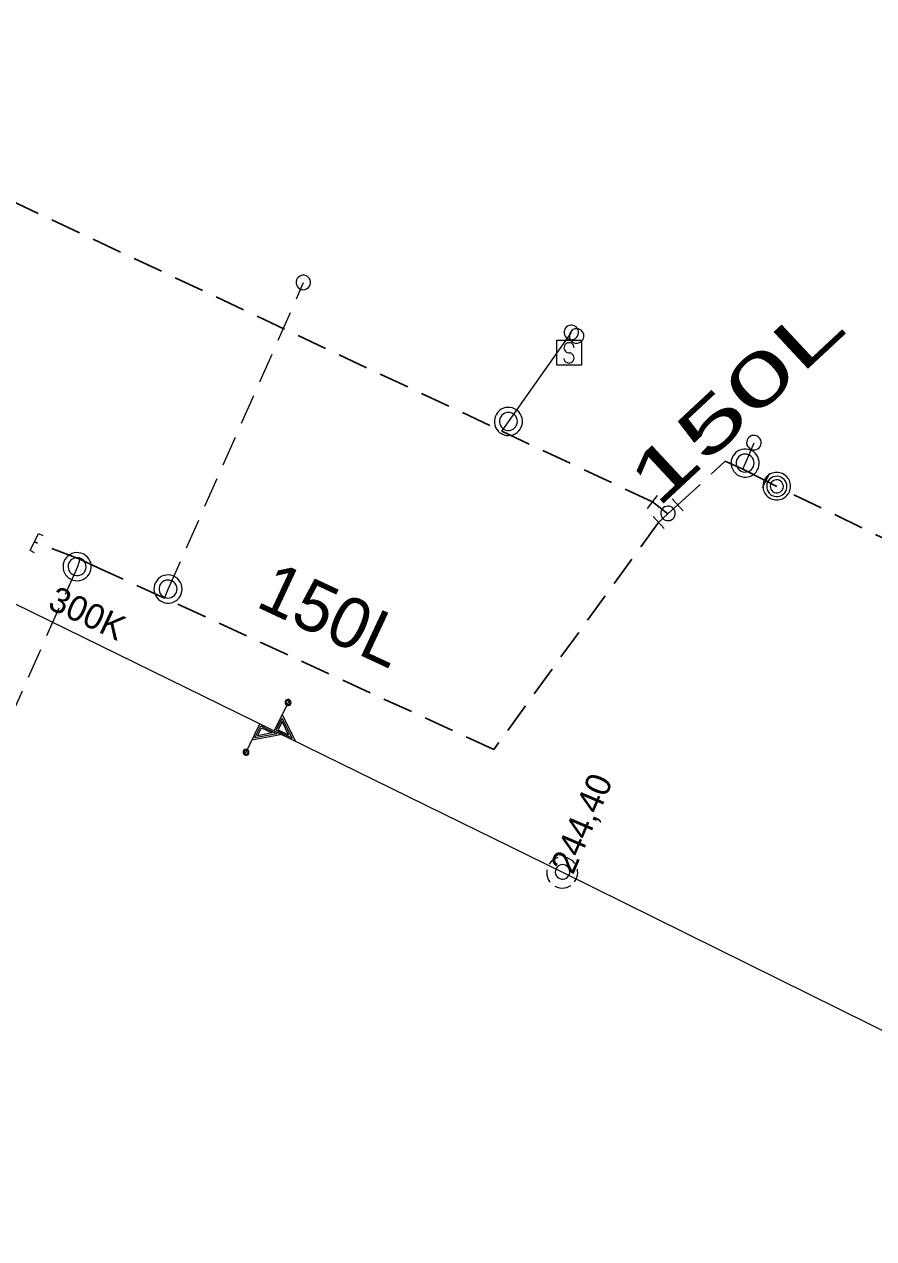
# Model space of a CAD drawing. Extents: x -735085 to -733500, y -1044153 to -1043402.
# Drawn here: x -734784.97 to -734758, y -1043597.02 to -1043558.45 of the extents above; entities that cross this region are included whole.
import ezdxf

# ---------------------------------------------------------------- set-up
doc = ezdxf.new("R2010")
doc.units = 0
doc.header["$LTSCALE"] = 0.32
doc.linetypes.add('MEDIUM_DASHED', pattern=[4.5, 3, -1.5])
doc.layers.add('15', color=7, linetype='Continuous')
doc.layers.add('16', color=7, linetype='Continuous')
for name, color, linetype, lineweight in [('18', 7, 'Continuous', 13), ('20', 7, 'Continuous', 13), ('8', 7, 'Continuous', 13)]:
    doc.layers.add(name, color=color, linetype=linetype, lineweight=lineweight)

msp = doc.modelspace()

# ---------------------------------------------------------------- linework, layer by layer
at = {"layer": '18'}
for points in [[(-734776.554, -1043579.904), (-734777.036, -1043580.888), (-734776.344, -1043581.227), (-734776.781, -1043580.369)], [(-734776.788, -1043580.498), (-734776.971, -1043580.871), (-734776.463, -1043581.121), (-734776.787, -1043580.496)], [(-734777.97, -1043581.655), (-734777.488, -1043580.672), (-734776.797, -1043581.011), (-734777.743, -1043581.191)], [(-734777.646, -1043581.107), (-734777.463, -1043580.734), (-734776.955, -1043580.983), (-734777.646, -1043581.108)], [(-734777.567, -1043581.052), (-734777.438, -1043580.79), (-734777.104, -1043580.954), (-734777.568, -1043581.052)], [(-734776.782, -1043580.593), (-734776.911, -1043580.855), (-734776.578, -1043581.019), (-734776.783, -1043580.593)], [(-734768.032, -1043584.917), (-734768.103, -1043584.945), (-734768.169, -1043584.984), (-734768.23, -1043585.032), (-734768.281, -1043585.089), (-734768.304, -1043585.123)], [(-734767.49, -1043585.1), (-734767.541, -1043585.042), (-734767.598, -1043584.992), (-734767.664, -1043584.951), (-734767.735, -1043584.922), (-734767.784, -1043584.908)], [(-734768.377, -1043585.309), (-734768.382, -1043585.386), (-734768.377, -1043585.463), (-734768.36, -1043585.538), (-734768.331, -1043585.609), (-734768.291, -1043585.675), (-734768.276, -1043585.697)], [(-734767.495, -1043585.686), (-734767.455, -1043585.621), (-734767.424, -1043585.551), (-734767.404, -1043585.476), (-734767.397, -1043585.4), (-734767.402, -1043585.323), (-734767.407, -1043585.288)], [(-734768.119, -1043585.826), (-734768.049, -1043585.857), (-734767.973, -1043585.876), (-734767.897, -1043585.883), (-734767.821, -1043585.878), (-734767.745, -1043585.861), (-734767.674, -1043585.833), (-734767.614, -1043585.798)]]:
    msp.add_lwpolyline(points, dxfattribs=at)
for points in [[(-734776.51, -1043580.031), (-734776.501, -1043579.998), (-734776.503, -1043579.965), (-734776.517, -1043579.935), (-734776.542, -1043579.911), (-734776.572, -1043579.898), (-734776.605, -1043579.896), (-734776.638, -1043579.906), (-734776.665, -1043579.926), (-734776.683, -1043579.954), (-734776.689, -1043579.987), (-734776.684, -1043580.02), (-734776.668, -1043580.049), (-734776.642, -1043580.071), (-734776.611, -1043580.082), (-734776.578, -1043580.082), (-734776.546, -1043580.07), (-734776.521, -1043580.048)], [(-734776.535, -1043580.021), (-734776.528, -1043579.993), (-734776.533, -1043579.965), (-734776.549, -1043579.942), (-734776.574, -1043579.927), (-734776.601, -1043579.924), (-734776.628, -1043579.931), (-734776.65, -1043579.95), (-734776.662, -1043579.976), (-734776.661, -1043580.005), (-734776.65, -1043580.03), (-734776.628, -1043580.049), (-734776.602, -1043580.058), (-734776.574, -1043580.054), (-734776.549, -1043580.039)], [(-734777.845, -1043581.612), (-734777.836, -1043581.58), (-734777.838, -1043581.546), (-734777.852, -1043581.516), (-734777.876, -1043581.493), (-734777.907, -1043581.479), (-734777.94, -1043581.477), (-734777.973, -1043581.487), (-734777.999, -1043581.507), (-734778.017, -1043581.536), (-734778.023, -1043581.568), (-734778.019, -1043581.602), (-734778.002, -1043581.631), (-734777.977, -1043581.652), (-734777.945, -1043581.664), (-734777.911, -1043581.664), (-734777.881, -1043581.651), (-734777.855, -1043581.629)], [(-734777.868, -1043581.599), (-734777.862, -1043581.572), (-734777.866, -1043581.544), (-734777.882, -1043581.521), (-734777.906, -1043581.506), (-734777.935, -1043581.502), (-734777.961, -1043581.512), (-734777.983, -1043581.53), (-734777.994, -1043581.556), (-734777.994, -1043581.583), (-734777.982, -1043581.609), (-734777.962, -1043581.628), (-734777.935, -1043581.637), (-734777.906, -1043581.633), (-734777.883, -1043581.619)], [(-734767.647, -1043585.369), (-734767.654, -1043585.317), (-734767.671, -1043585.267), (-734767.7, -1043585.223), (-734767.738, -1043585.186), (-734767.782, -1043585.159), (-734767.833, -1043585.143), (-734767.885, -1043585.138), (-734767.936, -1043585.145), (-734767.985, -1043585.164), (-734768.029, -1043585.194), (-734768.065, -1043585.233), (-734768.091, -1043585.278), (-734768.105, -1043585.329), (-734768.108, -1043585.381), (-734768.1, -1043585.433), (-734768.08, -1043585.481), (-734768.049, -1043585.524), (-734768.01, -1043585.559), (-734767.963, -1043585.583), (-734767.913, -1043585.597), (-734767.86, -1043585.599), (-734767.809, -1043585.589), (-734767.761, -1043585.567), (-734767.718, -1043585.535), (-734767.686, -1043585.495), (-734767.662, -1043585.448), (-734767.649, -1043585.397)]]:
    msp.add_lwpolyline(points, close=True, dxfattribs=at)
at = {"layer": '20'}
for p, q in [((-734802, -1043568.65), (-734767.879, -1043585.38)), ((-734802, -1043568.65), (-734767.879, -1043585.38)), ((-734767.879, -1043585.38), (-734722.55, -1043607.8)), ((-734767.879, -1043585.38), (-734722.55, -1043607.8))]:
    msp.add_line(p, q, dxfattribs=at)
at = {"layer": '8'}
for p, q in [((-734761.306, -1043572.715), (-734761.542, -1043573.174)), ((-734765.176, -1043573.827), (-734764.865, -1043573.414)), ((-734764.394, -1043573.516), (-734764.046, -1043573.899)), ((-734764.655, -1043574.46), (-734765.003, -1043574.078)), ((-734783.204, -1043575.44), (-734783.287, -1043575.682))]:
    msp.add_line(p, q, dxfattribs=at)
at = {"layer": '8', "linetype": 'MEDIUM_DASHED', "lineweight": 25}
for p, q in [((-734761.425, -1043572.947), (-734761.07, -1043573.13)), ((-734760.53, -1043573.392), (-734690.747, -1043607.257))]:
    msp.add_line(p, q, dxfattribs=at)
at = {"layer": '8', "lineweight": 25}
msp.add_line((-734764.829, -1043574.27), (-734764.53, -1043573.995), dxfattribs=at)
at = {"layer": '8', "linetype": 'MEDIUM_DASHED'}
msp.add_line((-734783.287, -1043575.682), (-734789.993, -1043590.765), dxfattribs=at)
at = {"layer": '8', "linetype": 'MEDIUM_DASHED', "lineweight": 25}
for points in [[(-734804.892, -1043550.168), (-734802.34, -1043556.09), (-734769.804, -1043571.373), (-734765.02, -1043573.62)], [(-734764.219, -1043573.71), (-734762.713, -1043572.326), (-734762.149, -1043572.574), (-734761.425, -1043572.947)], [(-734764.829, -1043574.27), (-734770.063, -1043581.483), (-734780.522, -1043576.674), (-734782.624, -1043575.708), (-734783.204, -1043575.44), (-734784.645, -1043574.891)]]:
    msp.add_lwpolyline(points, dxfattribs=at)
at = {"layer": '8', "linetype": 'MEDIUM_DASHED'}
msp.add_lwpolyline([(-734780.522, -1043576.674), (-734780.399, -1043576.39), (-734776.102, -1043566.655)], dxfattribs=at)
at = {"layer": '8'}
for points in [[(-734775.977, -1043566.46), (-734776.023, -1043566.435), (-734776.074, -1043566.421), (-734776.126, -1043566.418), (-734776.178, -1043566.428), (-734776.226, -1043566.449), (-734776.268, -1043566.48), (-734776.302, -1043566.52), (-734776.326, -1043566.567), (-734776.339, -1043566.618), (-734776.34, -1043566.671), (-734776.328, -1043566.722), (-734776.307, -1043566.769), (-734776.274, -1043566.811), (-734776.233, -1043566.843), (-734776.186, -1043566.867), (-734776.135, -1043566.877), (-734776.082, -1043566.878), (-734776.031, -1043566.865), (-734775.984, -1043566.841), (-734775.944, -1043566.808), (-734775.912, -1043566.766), (-734775.89, -1043566.718), (-734775.88, -1043566.666), (-734775.882, -1043566.614), (-734775.896, -1043566.564), (-734775.92, -1043566.517), (-734775.955, -1043566.478)], [(-734767.514, -1043568.021), (-734767.565, -1043568.007), (-734767.618, -1043568.006), (-734767.669, -1043568.016), (-734767.718, -1043568.037), (-734767.759, -1043568.069), (-734767.793, -1043568.11), (-734767.816, -1043568.156), (-734767.829, -1043568.207), (-734767.829, -1043568.26), (-734767.818, -1043568.312), (-734767.794, -1043568.359), (-734767.762, -1043568.399), (-734767.72, -1043568.432), (-734767.673, -1043568.454), (-734767.621, -1043568.466), (-734767.569, -1043568.464), (-734767.518, -1043568.452), (-734767.471, -1043568.427), (-734767.431, -1043568.393), (-734767.4, -1043568.351), (-734767.379, -1043568.303), (-734767.369, -1043568.251), (-734767.372, -1043568.199), (-734767.386, -1043568.148), (-734767.411, -1043568.102), (-734767.446, -1043568.063), (-734767.489, -1043568.033)], [(-734767.201, -1043568.348), (-734767.207, -1043568.296), (-734767.225, -1043568.246), (-734767.253, -1043568.202), (-734767.291, -1043568.165), (-734767.336, -1043568.138), (-734767.386, -1043568.122), (-734767.438, -1043568.117), (-734767.49, -1043568.124), (-734767.539, -1043568.143), (-734767.583, -1043568.173), (-734767.618, -1043568.212), (-734767.644, -1043568.257), (-734767.659, -1043568.308), (-734767.662, -1043568.36), (-734767.654, -1043568.412), (-734767.633, -1043568.46), (-734767.603, -1043568.503), (-734767.563, -1043568.538), (-734767.517, -1043568.562), (-734767.466, -1043568.576), (-734767.414, -1043568.578), (-734767.362, -1043568.568), (-734767.314, -1043568.546), (-734767.272, -1043568.514), (-734767.239, -1043568.474), (-734767.215, -1043568.427), (-734767.203, -1043568.376)], [(-734768.061, -1043568.479), (-734767.272, -1043568.479), (-734767.272, -1043569.279), (-734768.061, -1043569.279)], [(-734769.34, -1043570.697), (-734769.403, -1043570.66), (-734769.472, -1043570.634), (-734769.543, -1043570.619), (-734769.616, -1043570.616), (-734769.689, -1043570.625), (-734769.759, -1043570.645), (-734769.824, -1043570.677), (-734769.885, -1043570.719), (-734769.937, -1043570.771), (-734769.98, -1043570.83), (-734770.013, -1043570.896), (-734770.034, -1043570.966), (-734770.044, -1043571.037), (-734770.042, -1043571.111), (-734770.029, -1043571.183), (-734770.003, -1043571.251), (-734769.966, -1043571.315), (-734769.921, -1043571.372), (-734769.866, -1043571.421), (-734769.804, -1043571.459), (-734769.737, -1043571.487), (-734769.665, -1043571.505), (-734769.592, -1043571.51), (-734769.519, -1043571.502), (-734769.449, -1043571.484), (-734769.382, -1043571.454), (-734769.321, -1043571.414), (-734769.267, -1043571.364), (-734769.223, -1043571.306), (-734769.188, -1043571.241), (-734769.165, -1043571.171), (-734769.153, -1043571.099), (-734769.152, -1043571.026), (-734769.164, -1043570.954), (-734769.188, -1043570.884), (-734769.222, -1043570.82), (-734769.267, -1043570.762), (-734769.32, -1043570.713)], [(-734769.433, -1043570.829), (-734769.484, -1043570.8), (-734769.54, -1043570.783), (-734769.598, -1043570.776), (-734769.656, -1043570.783), (-734769.712, -1043570.799), (-734769.763, -1043570.828), (-734769.808, -1043570.867), (-734769.843, -1043570.914), (-734769.868, -1043570.966), (-734769.882, -1043571.024), (-734769.884, -1043571.082), (-734769.874, -1043571.139), (-734769.852, -1043571.194), (-734769.82, -1043571.243), (-734769.779, -1043571.285), (-734769.73, -1043571.317), (-734769.675, -1043571.338), (-734769.618, -1043571.349), (-734769.559, -1043571.346), (-734769.502, -1043571.332), (-734769.45, -1043571.307), (-734769.403, -1043571.271), (-734769.364, -1043571.227), (-734769.336, -1043571.177), (-734769.317, -1043571.121), (-734769.312, -1043571.063), (-734769.318, -1043571.004), (-734769.336, -1043570.949), (-734769.364, -1043570.898), (-734769.403, -1043570.854)], [(-734761.71, -1043571.524), (-734761.76, -1043571.509), (-734761.813, -1043571.506), (-734761.865, -1043571.514), (-734761.914, -1043571.535), (-734761.956, -1043571.565), (-734761.991, -1043571.605), (-734762.016, -1043571.651), (-734762.03, -1043571.702), (-734762.032, -1043571.754), (-734762.021, -1043571.806), (-734761.999, -1043571.854), (-734761.968, -1043571.895), (-734761.927, -1043571.929), (-734761.881, -1043571.953), (-734761.83, -1043571.966), (-734761.777, -1043571.965), (-734761.726, -1043571.955), (-734761.678, -1043571.932), (-734761.638, -1043571.899), (-734761.605, -1043571.857), (-734761.583, -1043571.81), (-734761.571, -1043571.759), (-734761.573, -1043571.706), (-734761.586, -1043571.655), (-734761.609, -1043571.609), (-734761.643, -1043571.568), (-734761.685, -1043571.537)], [(-734761.903, -1043571.974), (-734761.972, -1043571.95), (-734762.045, -1043571.939), (-734762.118, -1043571.939), (-734762.189, -1043571.952), (-734762.259, -1043571.975), (-734762.323, -1043572.01), (-734762.381, -1043572.055), (-734762.431, -1043572.108), (-734762.471, -1043572.169), (-734762.501, -1043572.237), (-734762.519, -1043572.307), (-734762.526, -1043572.381), (-734762.521, -1043572.453), (-734762.504, -1043572.524), (-734762.475, -1043572.592), (-734762.436, -1043572.653), (-734762.387, -1043572.708), (-734762.33, -1043572.754), (-734762.267, -1043572.79), (-734762.198, -1043572.815), (-734762.126, -1043572.829), (-734762.053, -1043572.831), (-734761.98, -1043572.821), (-734761.911, -1043572.798), (-734761.846, -1043572.765), (-734761.787, -1043572.722), (-734761.735, -1043572.67), (-734761.693, -1043572.61), (-734761.661, -1043572.544), (-734761.641, -1043572.474), (-734761.632, -1043572.401), (-734761.636, -1043572.328), (-734761.651, -1043572.256), (-734761.677, -1043572.188), (-734761.715, -1043572.125), (-734761.762, -1043572.069), (-734761.818, -1043572.022), (-734761.88, -1043571.984)], [(-734761.966, -1043572.122), (-734762.022, -1043572.104), (-734762.081, -1043572.099), (-734762.138, -1043572.104), (-734762.194, -1043572.123), (-734762.245, -1043572.151), (-734762.289, -1043572.19), (-734762.325, -1043572.236), (-734762.35, -1043572.29), (-734762.363, -1043572.346), (-734762.365, -1043572.405), (-734762.355, -1043572.463), (-734762.333, -1043572.517), (-734762.301, -1043572.566), (-734762.259, -1043572.608), (-734762.21, -1043572.639), (-734762.155, -1043572.661), (-734762.097, -1043572.67), (-734762.039, -1043572.668), (-734761.982, -1043572.653), (-734761.929, -1043572.628), (-734761.883, -1043572.592), (-734761.845, -1043572.548), (-734761.816, -1043572.497), (-734761.799, -1043572.442), (-734761.793, -1043572.383), (-734761.799, -1043572.325), (-734761.818, -1043572.269), (-734761.846, -1043572.219), (-734761.885, -1043572.175), (-734761.932, -1043572.14)], [(-734760.752, -1043573.126), (-734760.758, -1043573.065), (-734760.776, -1043573.005), (-734760.805, -1043572.95), (-734760.844, -1043572.902), (-734760.891, -1043572.862), (-734760.945, -1043572.832), (-734761.004, -1043572.812), (-734761.066, -1043572.805), (-734761.128, -1043572.809), (-734761.188, -1043572.825), (-734761.243, -1043572.853), (-734761.293, -1043572.89), (-734761.334, -1043572.937), (-734761.366, -1043572.99), (-734761.386, -1043573.049), (-734761.396, -1043573.11), (-734761.393, -1043573.172), (-734761.378, -1043573.232), (-734761.352, -1043573.289), (-734761.316, -1043573.339), (-734761.27, -1043573.382), (-734761.218, -1043573.414), (-734761.16, -1043573.437), (-734761.099, -1043573.447), (-734761.037, -1043573.446), (-734760.976, -1043573.433), (-734760.919, -1043573.408), (-734760.868, -1043573.373), (-734760.824, -1043573.329), (-734760.79, -1043573.277), (-734760.766, -1043573.22), (-734760.754, -1043573.159)], [(-734760.866, -1043573.126), (-734760.872, -1043573.077), (-734760.889, -1043573.03), (-734760.917, -1043572.989), (-734760.955, -1043572.956), (-734760.999, -1043572.932), (-734761.047, -1043572.92), (-734761.097, -1043572.919), (-734761.145, -1043572.931), (-734761.19, -1043572.953), (-734761.228, -1043572.986), (-734761.257, -1043573.026), (-734761.276, -1043573.073), (-734761.283, -1043573.122), (-734761.278, -1043573.172), (-734761.261, -1043573.219), (-734761.234, -1043573.261), (-734761.197, -1043573.295), (-734761.154, -1043573.319), (-734761.106, -1043573.333), (-734761.056, -1043573.334), (-734761.007, -1043573.324), (-734760.962, -1043573.302), (-734760.923, -1043573.27), (-734760.893, -1043573.231), (-734760.874, -1043573.185), (-734760.866, -1043573.135)], [(-734764.299, -1043573.984), (-734764.305, -1043573.932), (-734764.323, -1043573.882), (-734764.351, -1043573.838), (-734764.389, -1043573.801), (-734764.434, -1043573.774), (-734764.484, -1043573.758), (-734764.536, -1043573.753), (-734764.588, -1043573.76), (-734764.637, -1043573.779), (-734764.681, -1043573.809), (-734764.716, -1043573.848), (-734764.742, -1043573.893), (-734764.757, -1043573.944), (-734764.76, -1043573.996), (-734764.752, -1043574.048), (-734764.731, -1043574.096), (-734764.701, -1043574.139), (-734764.661, -1043574.174), (-734764.615, -1043574.198), (-734764.564, -1043574.212), (-734764.512, -1043574.214), (-734764.46, -1043574.204), (-734764.412, -1043574.182), (-734764.37, -1043574.15), (-734764.337, -1043574.11), (-734764.313, -1043574.063), (-734764.301, -1043574.012)], [(-734783.107, -1043575.27), (-734783.176, -1043575.245), (-734783.248, -1043575.232), (-734783.321, -1043575.23), (-734783.393, -1043575.241), (-734783.464, -1043575.262), (-734783.529, -1043575.295), (-734783.587, -1043575.338), (-734783.639, -1043575.39), (-734783.681, -1043575.45), (-734783.713, -1043575.517), (-734783.733, -1043575.587), (-734783.742, -1043575.66), (-734783.739, -1043575.732), (-734783.723, -1043575.804), (-734783.697, -1043575.873), (-734783.659, -1043575.935), (-734783.612, -1043575.991), (-734783.557, -1043576.039), (-734783.494, -1043576.077), (-734783.426, -1043576.104), (-734783.355, -1043576.119), (-734783.281, -1043576.123), (-734783.208, -1043576.115), (-734783.138, -1043576.095), (-734783.072, -1043576.064), (-734783.012, -1043576.022), (-734782.959, -1043575.971), (-734782.915, -1043575.912), (-734782.882, -1043575.847), (-734782.859, -1043575.777), (-734782.849, -1043575.705), (-734782.85, -1043575.632), (-734782.863, -1043575.56), (-734782.888, -1043575.491), (-734782.924, -1043575.427), (-734782.969, -1043575.37), (-734783.024, -1043575.321), (-734783.085, -1043575.282)], [(-734783.175, -1043575.417), (-734783.23, -1043575.398), (-734783.288, -1043575.39), (-734783.347, -1043575.394), (-734783.403, -1043575.411), (-734783.455, -1043575.438), (-734783.5, -1043575.476), (-734783.536, -1043575.521), (-734783.563, -1043575.574), (-734783.578, -1043575.63), (-734783.581, -1043575.689), (-734783.573, -1043575.747), (-734783.553, -1043575.802), (-734783.521, -1043575.851), (-734783.481, -1043575.894), (-734783.433, -1043575.927), (-734783.379, -1043575.95), (-734783.321, -1043575.961), (-734783.263, -1043575.961), (-734783.206, -1043575.948), (-734783.152, -1043575.924), (-734783.105, -1043575.89), (-734783.065, -1043575.846), (-734783.035, -1043575.796), (-734783.017, -1043575.741), (-734783.008, -1043575.683), (-734783.013, -1043575.625), (-734783.03, -1043575.568), (-734783.057, -1043575.517), (-734783.095, -1043575.472), (-734783.141, -1043575.436)], [(-734780.244, -1043575.97), (-734780.314, -1043575.949), (-734780.387, -1043575.939), (-734780.46, -1043575.942), (-734780.531, -1043575.956), (-734780.6, -1043575.982), (-734780.663, -1043576.018), (-734780.719, -1043576.065), (-734780.768, -1043576.12), (-734780.806, -1043576.182), (-734780.834, -1043576.251), (-734780.851, -1043576.322), (-734780.855, -1043576.395), (-734780.848, -1043576.467), (-734780.829, -1043576.538), (-734780.798, -1043576.605), (-734780.757, -1043576.665), (-734780.706, -1043576.718), (-734780.649, -1043576.763), (-734780.584, -1043576.797), (-734780.514, -1043576.82), (-734780.442, -1043576.831), (-734780.369, -1043576.831), (-734780.297, -1043576.819), (-734780.228, -1043576.795), (-734780.164, -1043576.76), (-734780.106, -1043576.715), (-734780.056, -1043576.661), (-734780.016, -1043576.6), (-734779.986, -1043576.533), (-734779.967, -1043576.462), (-734779.961, -1043576.389), (-734779.967, -1043576.316), (-734779.984, -1043576.245), (-734780.012, -1043576.178), (-734780.052, -1043576.116), (-734780.1, -1043576.061), (-734780.158, -1043576.016), (-734780.221, -1043575.98)], [(-734780.303, -1043576.12), (-734780.359, -1043576.104), (-734780.418, -1043576.1), (-734780.476, -1043576.107), (-734780.531, -1043576.127), (-734780.581, -1043576.157), (-734780.624, -1043576.197), (-734780.658, -1043576.245), (-734780.682, -1043576.299), (-734780.693, -1043576.356), (-734780.693, -1043576.415), (-734780.681, -1043576.472), (-734780.658, -1043576.526), (-734780.624, -1043576.573), (-734780.581, -1043576.614), (-734780.532, -1043576.644), (-734780.476, -1043576.664), (-734780.418, -1043576.672), (-734780.36, -1043576.668), (-734780.304, -1043576.652), (-734780.251, -1043576.625), (-734780.206, -1043576.588), (-734780.169, -1043576.542), (-734780.142, -1043576.491), (-734780.127, -1043576.435), (-734780.122, -1043576.376), (-734780.13, -1043576.318), (-734780.15, -1043576.263), (-734780.18, -1043576.213), (-734780.22, -1043576.171), (-734780.268, -1043576.137)]]:
    msp.add_lwpolyline(points, close=True, dxfattribs=at)
for points in [[(-734769.804, -1043571.373), (-734769.59, -1043571.07), (-734767.59, -1043568.24)], [(-734767.512, -1043568.725), (-734767.517, -1043568.682), (-734767.534, -1043568.641), (-734767.561, -1043568.607), (-734767.598, -1043568.581), (-734767.639, -1043568.566), (-734767.682, -1043568.563), (-734767.725, -1043568.571), (-734767.764, -1043568.591), (-734767.797, -1043568.62), (-734767.82, -1043568.658), (-734767.831, -1043568.7), (-734767.833, -1043568.743), (-734767.821, -1043568.786), (-734767.799, -1043568.823), (-734767.767, -1043568.854), (-734767.728, -1043568.874), (-734767.686, -1043568.883), (-734767.659, -1043568.883)], [(-734767.835, -1043569.062), (-734767.825, -1043569.105), (-734767.803, -1043569.144), (-734767.772, -1043569.175), (-734767.733, -1043569.196), (-734767.691, -1043569.207), (-734767.647, -1043569.205), (-734767.605, -1043569.192), (-734767.568, -1043569.168), (-734767.539, -1043569.135), (-734767.52, -1043569.095), (-734767.512, -1043569.052), (-734767.516, -1043569.008), (-734767.532, -1043568.967), (-734767.558, -1043568.932), (-734767.593, -1043568.905), (-734767.634, -1043568.888), (-734767.659, -1043568.883)], [(-734762.149, -1043572.574), (-734762.07, -1043572.39), (-734761.792, -1043571.741)], [(-734760.639, -1043573.118), (-734760.641, -1043573.073), (-734760.648, -1043573.028), (-734760.66, -1043572.983), (-734760.676, -1043572.941), (-734760.697, -1043572.9), (-734760.722, -1043572.861), (-734760.751, -1043572.826), (-734760.783, -1043572.793), (-734760.819, -1043572.765), (-734760.857, -1043572.74), (-734760.898, -1043572.719), (-734760.941, -1043572.702), (-734760.985, -1043572.69), (-734761.03, -1043572.683), (-734761.076, -1043572.681), (-734761.122, -1043572.683), (-734761.167, -1043572.69), (-734761.211, -1043572.702), (-734761.254, -1043572.719), (-734761.295, -1043572.74), (-734761.333, -1043572.765), (-734761.369, -1043572.793), (-734761.401, -1043572.826), (-734761.43, -1043572.861), (-734761.455, -1043572.9), (-734761.476, -1043572.941), (-734761.492, -1043572.983), (-734761.504, -1043573.028), (-734761.511, -1043573.073), (-734761.514, -1043573.119), (-734761.511, -1043573.164), (-734761.504, -1043573.209), (-734761.492, -1043573.254), (-734761.476, -1043573.296), (-734761.455, -1043573.337), (-734761.43, -1043573.376), (-734761.401, -1043573.411), (-734761.369, -1043573.444), (-734761.333, -1043573.472), (-734761.295, -1043573.497), (-734761.254, -1043573.518), (-734761.211, -1043573.535), (-734761.167, -1043573.546), (-734761.122, -1043573.554), (-734761.076, -1043573.556), (-734761.03, -1043573.554), (-734760.985, -1043573.546), (-734760.941, -1043573.535), (-734760.898, -1043573.518), (-734760.857, -1043573.497), (-734760.819, -1043573.472), (-734760.783, -1043573.444), (-734760.751, -1043573.411), (-734760.722, -1043573.376), (-734760.697, -1043573.337), (-734760.676, -1043573.296), (-734760.66, -1043573.254), (-734760.648, -1043573.209), (-734760.641, -1043573.164), (-734760.639, -1043573.119)], [(-734784.645, -1043575.235), (-734784.784, -1043575.167), (-734784.518, -1043574.621), (-734784.379, -1043574.689)]]:
    msp.add_lwpolyline(points, dxfattribs=at)
at = {"layer": '8', "lineweight": 25}
msp.add_lwpolyline([(-734765.02, -1043573.62), (-734764.53, -1043573.995), (-734764.219, -1043573.71)], dxfattribs=at)

# ---------------------------------------------------------------- texts
at = {"layer": '15', "width": 1.75}
msp.add_text('150L', height=1.6, rotation=43, dxfattribs=at).set_placement((-734764.879, -1043573.861))
at = {"layer": '15'}
msp.add_text('150L', height=1.6, rotation=335, dxfattribs=at).set_placement((-734777.664, -1043576.923))
at = {"layer": '16'}
for s, rotation, p in [('300K', 335, (-734784.267, -1043576.988)), ('244,40', 67, (-734767.546, -1043585.487))]:
    msp.add_text(s, height=0.8, rotation=rotation, dxfattribs=at).set_placement(p)

doc.saveas('drawing.dxf')
